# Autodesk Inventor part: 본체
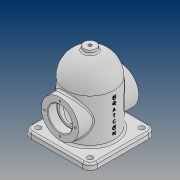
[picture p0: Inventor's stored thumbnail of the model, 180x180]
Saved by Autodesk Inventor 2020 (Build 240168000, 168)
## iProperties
Created: 2021-08
Part Number: 본체
Material: 일반
Document SubType Name: Modeling
Designer: PC312-
Density: 1 g/cm^3
Appearance: 기본값
Author: PC312-
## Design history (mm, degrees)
sketch "스케치2"
  geometry: C1 r 40 at (0, 0); 1 further point
  constraints: 1 centre point, 1 coincident
  dimensions: "d0" = 80 diameter of C1
extrude "돌출1" new body sketch "스케치2" distance "d1" = 84; taper "d2" = 0 deg
sketch "스케치3"
  geometry: L1 (40, 0)-(-40, 0); L2 (40, 84)-(-40, 84) reference; L3 (0, 124)-(0, 84); A1 r 40 centre (0, 84) between (0, 124) and (-40, 84); 2 further points
  constraints: 2 end point, 2 point on circle, 1 centre point, 1 midpoint, 1 point on line, 1 vertical
  dimensions: "d4" = 40 radius of A1
revolve "회전1" sketch "스케치3" stored, may be unused: angle "d5" = 360 deg
feature "쉘1" dims "d7" = 8
sketch "스케치5"
  geometry: L1 (-55, 55)-(55, 55); L2 (55, 55)-(55, -55); L3 (55, -55)-(-55, -55); L4 (-55, -55)-(-55, 55); L5 (-55, 55)-(55, -55); L6 (55, 55)-(-55, -55); C1 r 32 at (0, 0) reference; 1 further point
  constraints: 12 end point, 2 midpoint, 2 parallel, 1 horizontal, 1 perpendicular
  dimensions: "d8" = 110 distance of L2.end L3.end; "d9" = 110 distance of L1.end L2.end
extrude "돌출2" cut sketch "스케치5" distance "d10" = 10; taper "d11" = 0 deg
extrude "돌출3" join sketch "스케치5" distance "d12" = 10; taper "d13" = 0 deg
node "작업 평면1"
sketch "스케치6"
  geometry: C1 r 10 at (0, 0); 1 further point
  constraints: 1 centre point, 1 coincident
  dimensions: "d15" = 20 diameter of C1
extrude "돌출4" join sketch "스케치6" stored distance "d16" = 10; taper "d17" = 0 deg
sketch "스케치7"
  geometry: C1 r 10 at (0, 0) reference; 2 further points
  constraints: 1 coincident
hole "구멍1" sketch "스케치7" at (0, 0) diameter "d18" = 5.1881; stored, may be unused: countersink angle "d22" = 90 deg, drill point angle "d24" = 0 deg; dims "d19" = 12, "d20" = 4, "d21" = 2, "d23" = 16
node "작업 평면2"
sketch "스케치8"
  geometry: L1 (55, 0)-(-55, 0) reference; C1 r 31 at (0, 48); 2 further points
  constraints: 1 centre point, 1 midpoint, 1 vertical alignment
  dimensions: "d26" = 62 diameter of C1; "d27" = 48 distance from line of L1 C1.centre
extrude "돌출5" join sketch "스케치8" stored distance "d28" = 10; taper "d29" = 0 deg
sketch "스케치9"
  geometry: C1 r 20 at (0, 0); C2 r 31 at (0, 0) reference; 1 further point
  constraints: 1 centre point, 1 concentric
  dimensions: "d30" = 40 diameter of C1
extrude "돌출6" cut sketch "스케치9" distance "d31" = 15; taper "d32" = 0 deg
sketch "스케치10" dims "d33" = 51
  geometry: C1 r 31 at (0, 0) reference; 3 further points
  constraints: 2 vertical alignment, 3 other
hole "구멍2" sketch "스케치10" at (0, 25.5) diameter "d34" = 3.242; stored, may be unused: countersink angle "d38" = 90 deg, drill point angle "d40" = 118 deg; dims "d35" = 8, "d36" = 4, "d37" = 2, "d39" = 10
sketch "스케치11"
  geometry: C1 r 16.5 at (0, 0); C2 r 20 at (0, 0) reference; 1 further point
  constraints: 1 centre point, 1 concentric
  dimensions: "d44" = 33 diameter of C1
extrude "돌출7" cut sketch "스케치11" extent not by distance; stored distance "d45" = 15; taper "d46" = 0 deg
fillet "모깎기1" dims "d47" = 12
sketch "스케치13"
  geometry: C1 r 4.5 at (-43, -43); C2 r 4.5 at (-43, 43); C3 r 4.5 at (43, -43); C4 r 4.5 at (43, 43); A1 r 12 centre (-43, -43) between (-55, -43) and (-43, -55) reference; A2 r 12 centre (-43, 43) between (-43, 55) and (-55, 43) reference; A3 r 12 centre (43, -43) between (43, -55) and (55, -43) reference; A4 r 12 centre (43, 43) between (55, 43) and (43, 55) reference; 1 further point
  constraints: 4 centre point, 4 concentric
  dimensions: "d48" = 9 diameter of C1; "d49" = 9 diameter of C2; "d50" = 9 diameter of C3; "d51" = 9 diameter of C4
extrude "돌출8" cut sketch "스케치13" distance "d52" = 15; taper "d53" = 0 deg
chamfer "모따기1" distance "d54" = 1; stored, may be unused: second distance "d55" = 2, angle "d56" = 45 deg
fillet "모깎기2" dims "d57" = 3
fillet "모깎기3" dims "d58" = 3
fillet "모깎기4" dims "d59" = 3
node "작업 평면3"
sketch "스케치14"
  geometry: L1 (0, -43)-(0, 43) reference; 4 further points
  constraints: 2 midpoint, 1 horizontal alignment, 1 other
  dimensions: "d62" = 48 distance from line of L1 point (48, 0)
feature "엠보싱1" sketch "스케치14" dims "d8" = 110, "d9" = 110, "d63" = 0.5, "d64" = 0
fillet "모깎기5" dims "d65" = 3
fillet "모깎기6" dims "d66" = 0.3
node "솔리드1"
mirror "미러1"
pattern_circular "원형 패턴1" dims angle "d42" = 360 deg
mirror "미러2"
feature "A9D066F2-1C7D-4E18-AEED-F7BC21143FA4" dims "d34" = 3.242, "d35" = 8, "d36" = 4, "d37" = 2, "d38" = 90 deg, "d39" = 10, "d40" = 118 deg
other parameters: "d14" = -129, "d60" = 52.25
